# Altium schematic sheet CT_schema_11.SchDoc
size 389 x 278 mm
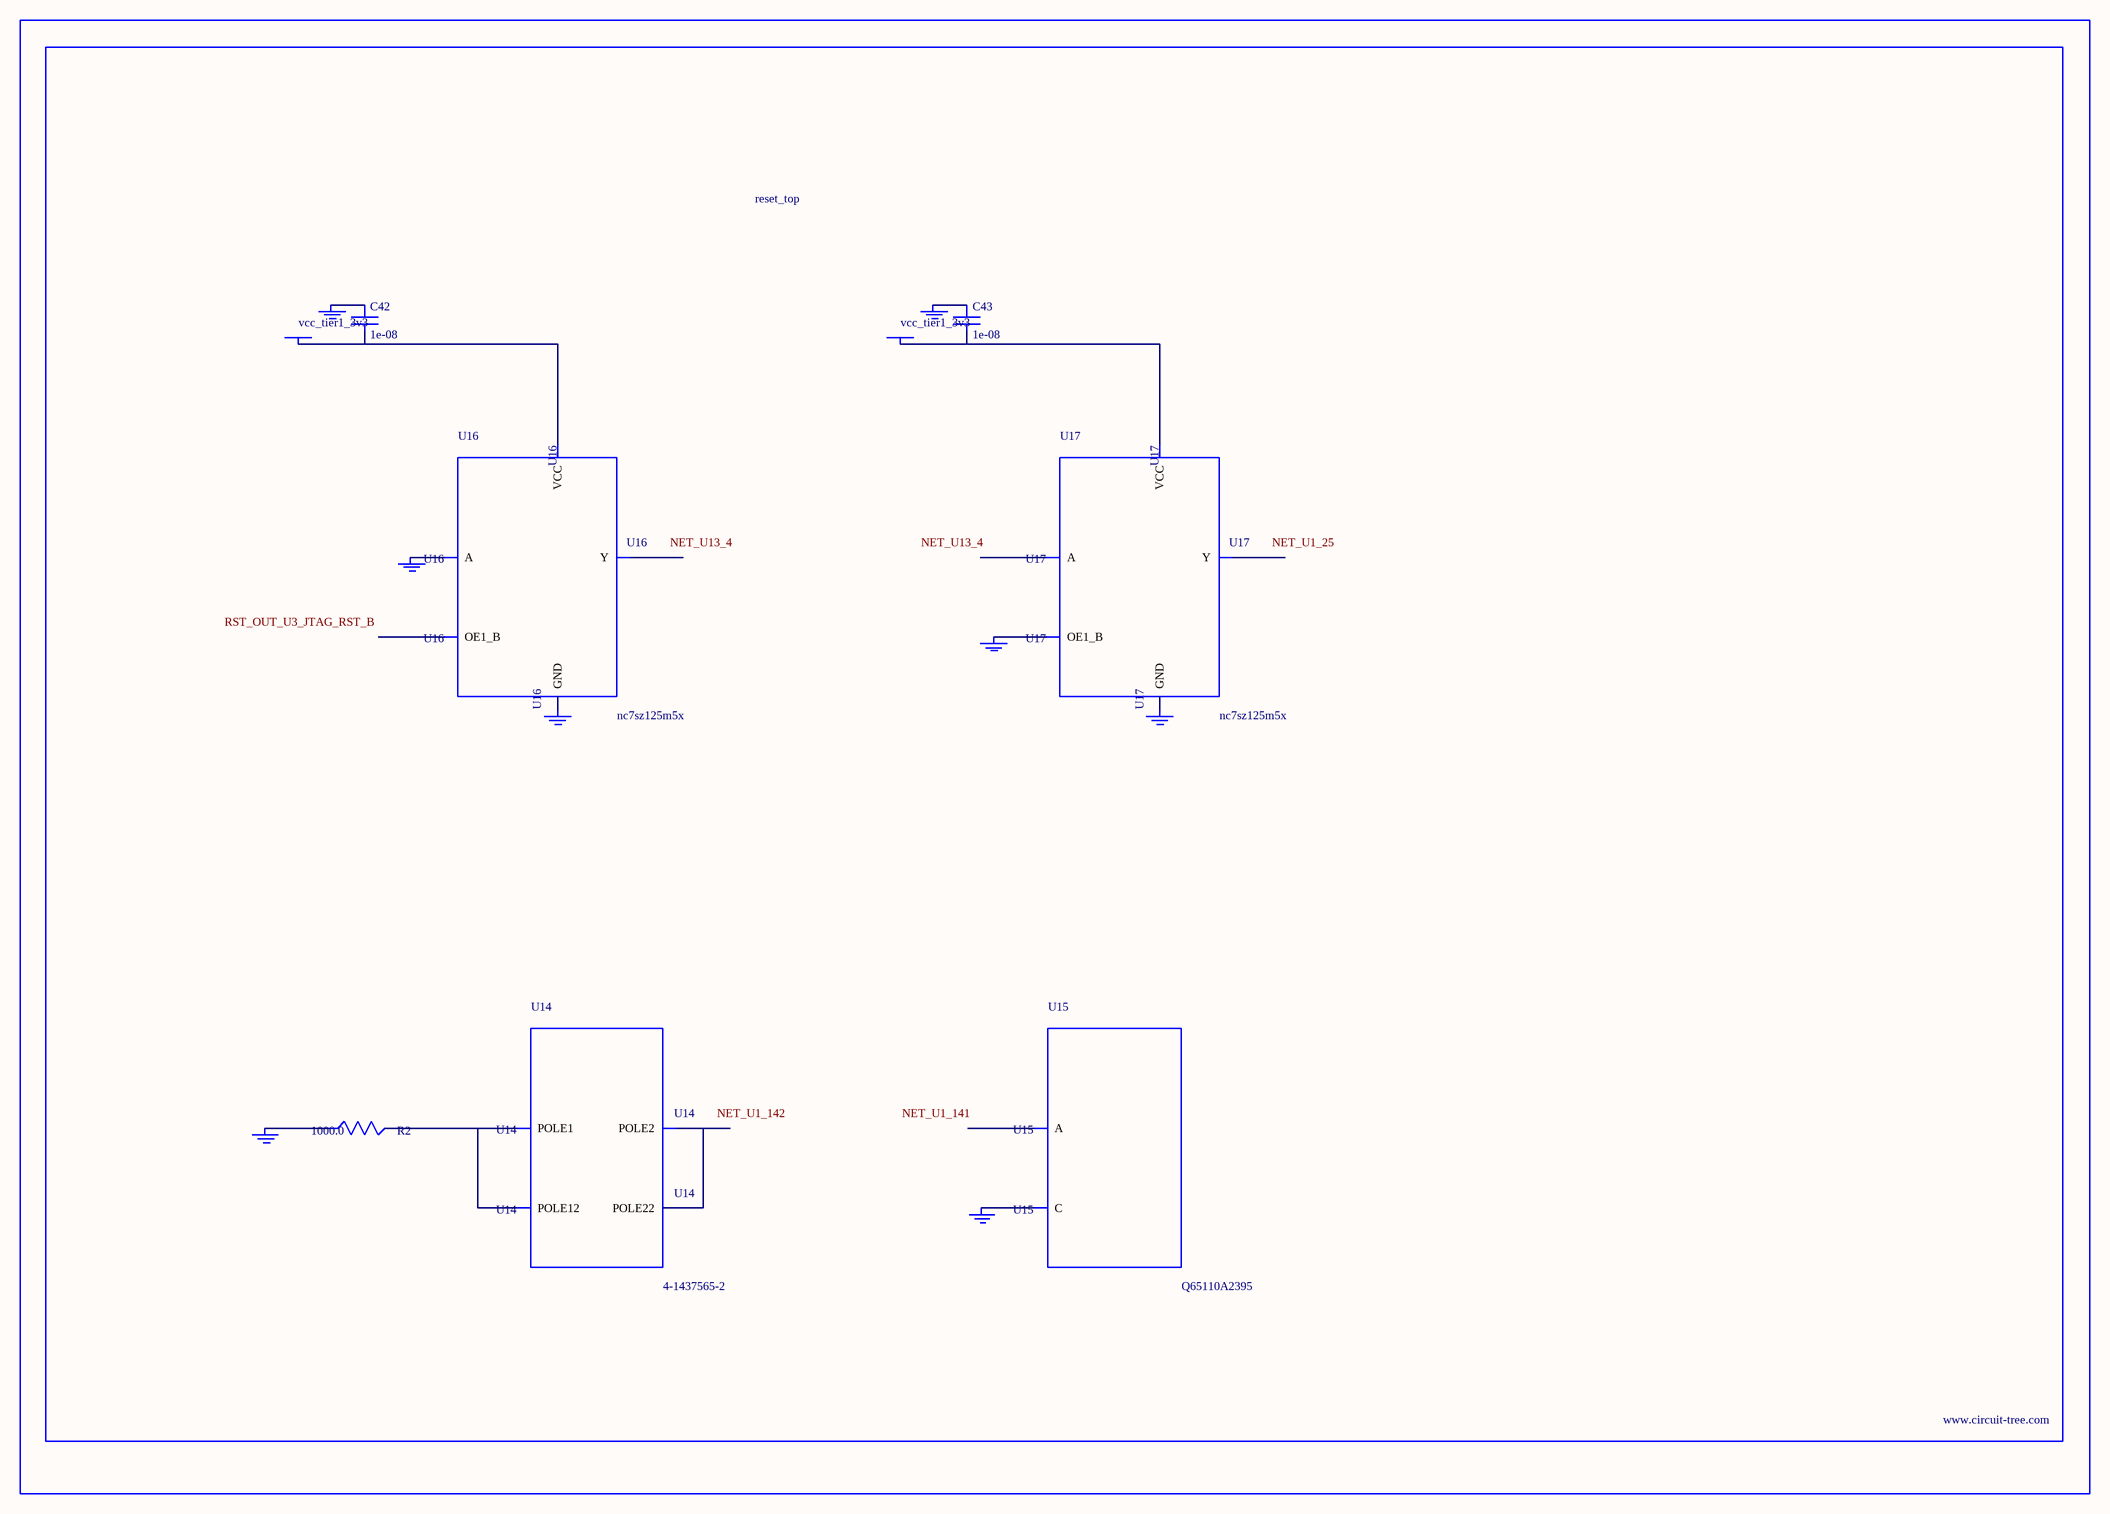
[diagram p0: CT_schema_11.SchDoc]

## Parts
BORDER10  (no value)
C42  1e-08  [C0402]
C43  1e-08  [C0402]
GND_INSTANCE_10_0  (no value)
GND_INSTANCE_10_1  (no value)
GND_INSTANCE_10_2  (no value)
GND_INSTANCE_10_3  (no value)
GND_INSTANCE_10_4  (no value)
GND_INSTANCE_10_5  (no value)
GND_INSTANCE_10_6  (no value)
GND_INSTANCE_10_7  (no value)
POWER_INSTANCE_10_0  vcc_tier1_3v3
POWER_INSTANCE_10_1  vcc_tier1_3v3
R2  1000.0  [R0603]
U14  4-1437565-2  [SW_4-1437565-2]
U15  Q65110A2395  [LGM67K-G1J2-24-Z]
U16  nc7sz125m5x  [NC7SZ125M5X]
U17  nc7sz125m5x  [NC7SZ125M5X]

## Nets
NetC42_1: C42.1 GND_INSTANCE_10_2.0(GND)
NetC42_2: C42.2 POWER_INSTANCE_10_0.0(PWR) U16.5(VCC)
NetC43_1: C43.1 GND_INSTANCE_10_5.0(GND)
NetC43_2: C43.2 POWER_INSTANCE_10_1.0(PWR) U17.5(VCC)
NetGND_INSTANCE_10_0_0: GND_INSTANCE_10_0.0(GND) R2.1
NetGND_INSTANCE_10_1_0: GND_INSTANCE_10_1.0(GND) U15.C
NetGND_INSTANCE_10_3_0: GND_INSTANCE_10_3.0(GND) U16.2(A)
NetGND_INSTANCE_10_4_0: GND_INSTANCE_10_4.0(GND) U16.3(GND)
NetGND_INSTANCE_10_6_0: GND_INSTANCE_10_6.0(GND) U17.1(OE1_B)
NetGND_INSTANCE_10_7_0: GND_INSTANCE_10_7.0(GND) U17.3(GND)
NetR2_2: R2.2 U14.1(POLE1) U14.2(POLE12)
NetU14_3: U14.3(POLE2) U14.4(POLE22)

Not connected (* = marked no-connect by the designer): U15 A; U16 1(OE1_B) 4(Y); U17 2(A) 4(Y)

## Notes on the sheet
- Labels drawn without touching a wire or pin: NET_U1_25, NET_U1_141, NET_U1_142, NET_U13_4, RST_OUT_U3_JTAG_RST_B

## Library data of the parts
BORDER10 = BORDER_PAGE10
C42 C43 = C0402C103K3RAC
GND_INSTANCE_10_0-GND_INSTANCE_10_7 = GND
POWER_INSTANCE_10_0 POWER_INSTANCE_10_1 = PWR
R2 = RC0603JR-071KL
